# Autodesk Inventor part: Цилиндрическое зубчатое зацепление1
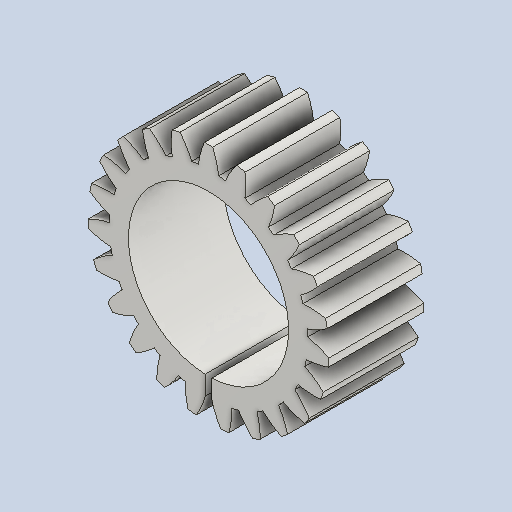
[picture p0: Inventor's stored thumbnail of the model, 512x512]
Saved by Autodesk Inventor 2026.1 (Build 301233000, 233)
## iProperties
Created: 2026-01
Part Number: Цилиндрическое зубчатое зацепление1
Material: Steel
Document SubType Name: Modeling
Designer: Yury Melnikov
Categories: <?xml version="1.0" encoding="UTF-16"?> <MemberInstance><Categories><FamilyTemplate><FamilyTemplateParameter ValueType="xs:double" Id="1" ObjectReferenceKey="da
Density: 1 g/cm^3
Appearance: Steel
CustomPartVersion: 1
Author: Yury Melnikov
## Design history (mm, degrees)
sketch "Sketch1"
  geometry: C1 r 25.373 at (0, 0)
  constraints: 1 centre point
  dimensions: "d0" = 50.74635 diameter of C1 (= da_da)
extrude "Extrusion1" new body sketch "Sketch1" distance "d1" = 20 (= da_b); taper "d2" = 0 deg
workplane "Work Plane2"
feature "Средний диаметр" dims "d4" = 10, "d5" = 0
workplane "Work Plane8"
workplane "Work Plane9"
feature "Цилиндрическое зубчатое зацепление" dims "da_b" = 20, "da_d" = 46, "da_aw" = 32.28494, "da_da" = 50.74635, "da_df" = 41.74635, "da_dw" = 43.67963, angle "da_beta" = 0 deg, "da_lefttooth" = 0, "da_righttooth" = 0
sketch "Эскиз3"
  geometry: C1 r 16.873 at (0, 0); A1 r 20.873 centre (0, 0) between (-12.612, 16.632) and (-13.718, 15.732) reference; 1 further point
  constraints: 1 centre point, 1 coincident
  dimensions: "d49" = 4 radial gap between concentric circles of C1 A1
extrude "Выдавливание2" cut sketch "Эскиз3" distance "d50" = 24.25; taper "d51" = 0 deg
sketch "Эскиз4"
  geometry: L1 (-0.713, -16.432)-(0.713, -16.432); L2 (0.713, -16.432)-(0.713, -21.161); L3 (0.713, -21.161)-(-0.713, -21.161); L4 (-0.713, -21.161)-(-0.713, -16.432); 3 further points
  constraints: 8 end point, 2 parallel, 2 point on line, 1 horizontal, 1 perpendicular
extrude "Выдавливание3" cut sketch "Эскиз4" distance "d52" = 24.25; taper "d53" = 0 deg
body "Solid1"
sketch "Sketch2"
  geometry: C1 r 25.373 at (0, 0) reference; C2 r 23 at (0, 0)
  constraints: 1 centre point, 1 coincident
  dimensions: "d3" = 46 diameter of C2 (= da_d)
body "Srf1"
other parameters: "d16" = 32.28494 (= da_aw), "d17" = 0, "d34" = 1.36591 (computed from da_z), "d39" = 0, "d41" = 0, "d43" = 32.28494 (= da_aw), "d46" = 32.28494 (= da_aw), "d47" = 0, "d48" = 0
